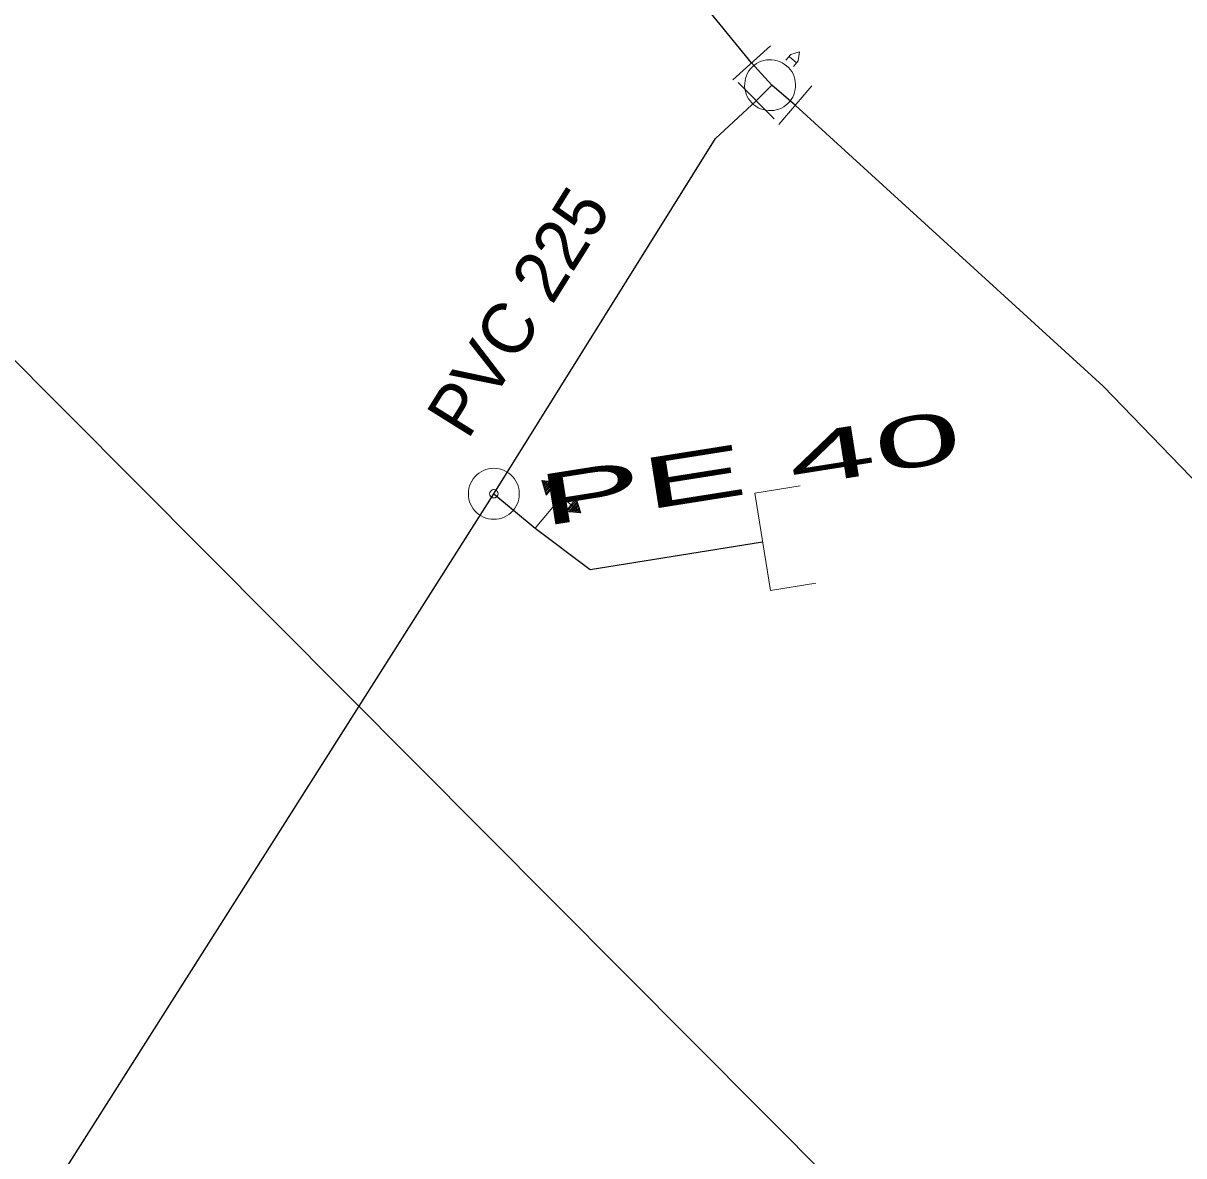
# Model space of a CAD drawing. Extents: x -659250 to -657316, y -997555 to -993684.
# Drawn here: x -658188.9 to -658166.14, y -996491.07 to -996468.86 of the extents above; entities that cross this region are included whole.
import ezdxf

# ---------------------------------------------------------------- set-up
doc = ezdxf.new("R2010")
doc.units = 0
doc.header["$LTSCALE"] = 0.4
doc.layers.add('1', color=7, linetype='Continuous')
for name, color, linetype, lineweight in [('14', 7, 'Continuous', 25), ('17', 7, 'Continuous', 25), ('23', 7, 'Continuous', 13), ('34', 7, 'Continuous', 13), ('42', 7, 'Continuous', 13), ('47', 7, 'Continuous', 13)]:
    doc.layers.add(name, color=color, linetype=linetype, lineweight=lineweight)

msp = doc.modelspace()

# ---------------------------------------------------------------- linework, layer by layer
at = {"layer": '14', "lineweight": 13}
msp.add_line((-658174.53, -996470.376), (-658174.221, -996470.07), dxfattribs=at)
at = {"layer": '14'}
msp.add_line((-658153.802, -996510.91), (-658194.34, -996470.18), dxfattribs=at)
at = {"layer": '17'}
for p, q in [((-658174.221, -996470.07), (-658174.617, -996469.633)), ((-658173.758, -996470.467), (-658174.221, -996470.07)), ((-658179.673, -996478.088), (-658178.86, -996478.761))]:
    msp.add_line(p, q, dxfattribs=at)
for points in [[(-658174.617, -996469.633), (-658187.469, -996453.91), (-658187.489, -996453.649)], [(-658179.673, -996478.088), (-658175.322, -996471.116), (-658174.53, -996470.376)], [(-658015.694, -996748.132), (-658012.013, -996715.116), (-658013.6, -996700.998), (-658031.362, -996648.688), (-658043.62, -996623.609), (-658054.721, -996612.745), (-658075.467, -996597.998), (-658101.14, -996577.425), (-658112.195, -996565.522), (-658140.875, -996516.98), (-658153.131, -996491.09), (-658167.719, -996475.975), (-658173.758, -996470.467)], [(-658341.671, -996632.003), (-658299.065, -996610.892), (-658296.028, -996615.664), (-658262.818, -996595.147), (-658215.971, -996543.456), (-658200.249, -996510.524), (-658179.673, -996478.088)], [(-658178.86, -996478.761), (-658177.783, -996479.576), (-658174.4, -996479.031)]]:
    msp.add_lwpolyline(points, dxfattribs=at)
at = {"layer": '23'}
msp.add_line((-658173.734, -996469.634), (-658173.883, -996469.506), dxfattribs=at)
for points in [[(-658173.946, -996469.58), (-658173.849, -996469.467), (-658173.675, -996469.417), (-658173.7, -996469.594), (-658173.797, -996469.708)], [(-658173.87, -996470.393), (-658173.838, -996470.351), (-658173.811, -996470.306), (-658173.79, -996470.259), (-658173.773, -996470.209), (-658173.761, -996470.159), (-658173.755, -996470.106), (-658173.754, -996470.054), (-658173.759, -996470.002), (-658173.768, -996469.951), (-658173.783, -996469.901), (-658173.804, -996469.852), (-658173.83, -996469.806), (-658173.859, -996469.763), (-658173.893, -996469.725), (-658173.931, -996469.689), (-658173.975, -996469.657), (-658174.018, -996469.63), (-658174.067, -996469.608), (-658174.114, -996469.591), (-658174.166, -996469.578), (-658174.219, -996469.573), (-658174.271, -996469.572), (-658174.324, -996469.577), (-658174.375, -996469.586), (-658174.424, -996469.602), (-658174.473, -996469.623), (-658174.518, -996469.648), (-658174.561, -996469.678), (-658174.6, -996469.713), (-658174.636, -996469.751), (-658174.668, -996469.792), (-658174.695, -996469.837), (-658174.717, -996469.885), (-658174.734, -996469.934), (-658174.744, -996469.985), (-658174.751, -996470.037), (-658174.753, -996470.089), (-658174.748, -996470.142), (-658174.738, -996470.193)], [(-658174.067, -996469.608), (-658174.114, -996469.591), (-658174.166, -996469.578), (-658174.219, -996469.573), (-658174.271, -996469.572), (-658174.324, -996469.577), (-658174.375, -996469.586), (-658174.424, -996469.602), (-658174.473, -996469.623), (-658174.518, -996469.648), (-658174.561, -996469.678), (-658174.6, -996469.713), (-658174.636, -996469.751), (-658174.668, -996469.792), (-658174.695, -996469.837), (-658174.717, -996469.885), (-658174.734, -996469.934), (-658174.744, -996469.985), (-658174.751, -996470.037), (-658174.753, -996470.089), (-658174.748, -996470.142), (-658174.738, -996470.193), (-658174.723, -996470.242), (-658174.702, -996470.291), (-658174.678, -996470.337), (-658174.646, -996470.38), (-658174.612, -996470.418), (-658174.574, -996470.454), (-658174.532, -996470.485), (-658174.488, -996470.513), (-658174.44, -996470.536), (-658174.39, -996470.552), (-658174.339, -996470.564), (-658174.288, -996470.571), (-658174.235, -996470.57), (-658174.183, -996470.567), (-658174.132, -996470.557), (-658174.081, -996470.541), (-658174.033, -996470.521), (-658173.987, -996470.495)], [(-658174.738, -996470.193), (-658174.723, -996470.242), (-658174.702, -996470.291), (-658174.678, -996470.337), (-658174.646, -996470.38), (-658174.612, -996470.418), (-658174.574, -996470.454), (-658174.532, -996470.485), (-658174.488, -996470.513), (-658174.44, -996470.536), (-658174.39, -996470.552), (-658174.339, -996470.564), (-658174.288, -996470.571), (-658174.235, -996470.57), (-658174.183, -996470.567), (-658174.132, -996470.557), (-658174.081, -996470.541), (-658174.033, -996470.521), (-658173.987, -996470.495), (-658173.945, -996470.464), (-658173.906, -996470.431), (-658173.87, -996470.393), (-658173.838, -996470.351), (-658173.811, -996470.306), (-658173.79, -996470.259), (-658173.773, -996470.209), (-658173.761, -996470.159), (-658173.755, -996470.106), (-658173.754, -996470.054), (-658173.759, -996470.002), (-658173.768, -996469.951), (-658173.783, -996469.901), (-658173.804, -996469.852), (-658173.83, -996469.806), (-658173.859, -996469.763), (-658173.893, -996469.725), (-658173.931, -996469.689), (-658173.975, -996469.657), (-658174.018, -996469.63), (-658174.067, -996469.608)], [(-658173.987, -996470.495), (-658173.945, -996470.464), (-658173.906, -996470.431), (-658173.87, -996470.393)]]:
    msp.add_lwpolyline(points, dxfattribs=at)
at = {"layer": '34'}
for p, q in [((-658174.246, -996469.297), (-658174.988, -996469.967)), ((-658174.882, -996470.021), (-658174.177, -996470.731)), ((-658173.432, -996470.087), (-658174.083, -996470.846)), ((-658178.648, -996478.114), (-658178.73, -996477.828)), ((-658178.702, -996477.83), (-658178.722, -996477.855)), ((-658178.67, -996477.837), (-658178.711, -996477.885)), ((-658178.639, -996477.838), (-658178.705, -996477.916)), ((-658178.612, -996477.84), (-658178.698, -996477.943)), ((-658178.58, -996477.847), (-658178.688, -996477.973)), ((-658178.553, -996477.849), (-658178.68, -996477.999)), ((-658178.524, -996477.853), (-658178.672, -996478.027)), ((-658178.492, -996477.853), (-658178.666, -996478.058)), ((-658178.462, -996477.859), (-658178.655, -996478.087)), ((-658178.348, -996478.145), (-658178.859, -996478.76)), ((-658178.047, -996478.204), (-658178.235, -996478.436)), ((-658178.035, -996478.233), (-658178.204, -996478.441)), ((-658178.03, -996478.263), (-658178.173, -996478.441)), ((-658178.02, -996478.291), (-658178.144, -996478.444)), ((-658178.013, -996478.318), (-658178.117, -996478.447)), ((-658178.001, -996478.347), (-658178.085, -996478.451)), ((-658177.993, -996478.374), (-658178.057, -996478.453)), ((-658177.987, -996478.404), (-658178.026, -996478.453)), ((-658177.974, -996478.434), (-658177.994, -996478.459))]:
    msp.add_line(p, q, dxfattribs=at)
for points in [[(-658178.73, -996477.828), (-658178.433, -996477.862), (-658178.648, -996478.114)], [(-658178.263, -996478.433), (-658177.967, -996478.461), (-658178.73, -996477.828)], [(-658177.967, -996478.461), (-658178.055, -996478.176), (-658178.263, -996478.433)]]:
    msp.add_lwpolyline(points, dxfattribs=at)
at = {"layer": '42'}
msp.add_lwpolyline([(-658173.664, -996477.934), (-658174.553, -996478.077), (-658174.247, -996479.984), (-658173.357, -996479.841)], dxfattribs=at)
at = {"layer": '47'}
for points in [[(-658179.173, -996478.088), (-658179.176, -996478.036), (-658179.184, -996477.983), (-658179.198, -996477.934), (-658179.215, -996477.885), (-658179.24, -996477.838), (-658179.269, -996477.794), (-658179.301, -996477.754), (-658179.338, -996477.717), (-658179.379, -996477.684), (-658179.423, -996477.655), (-658179.47, -996477.63), (-658179.519, -996477.613), (-658179.568, -996477.599), (-658179.62, -996477.591), (-658179.673, -996477.588), (-658179.725, -996477.591), (-658179.777, -996477.599), (-658179.828, -996477.613), (-658179.875, -996477.63), (-658179.923, -996477.655), (-658179.967, -996477.684), (-658180.007, -996477.717), (-658180.044, -996477.754), (-658180.078, -996477.794), (-658180.105, -996477.838), (-658180.13, -996477.885), (-658180.149, -996477.934), (-658180.161, -996477.983), (-658180.169, -996478.036), (-658180.173, -996478.088), (-658180.169, -996478.14), (-658180.161, -996478.192), (-658180.149, -996478.243), (-658180.13, -996478.291), (-658180.105, -996478.338), (-658180.078, -996478.382), (-658180.044, -996478.423), (-658180.007, -996478.46), (-658179.967, -996478.493), (-658179.923, -996478.521), (-658179.875, -996478.545), (-658179.828, -996478.564), (-658179.777, -996478.576), (-658179.725, -996478.585), (-658179.673, -996478.588), (-658179.62, -996478.585), (-658179.568, -996478.576), (-658179.519, -996478.564), (-658179.47, -996478.545), (-658179.423, -996478.521), (-658179.379, -996478.493), (-658179.338, -996478.46), (-658179.301, -996478.423), (-658179.269, -996478.382), (-658179.24, -996478.338), (-658179.215, -996478.291), (-658179.198, -996478.243), (-658179.184, -996478.192), (-658179.176, -996478.14)], [(-658179.59, -996478.088), (-658179.59, -996478.079), (-658179.593, -996478.071), (-658179.595, -996478.063), (-658179.598, -996478.054), (-658179.602, -996478.047), (-658179.607, -996478.04), (-658179.612, -996478.032), (-658179.617, -996478.027), (-658179.625, -996478.022), (-658179.632, -996478.017), (-658179.639, -996478.013), (-658179.647, -996478.01), (-658179.656, -996478.008), (-658179.664, -996478.005), (-658179.673, -996478.005), (-658179.681, -996478.005), (-658179.69, -996478.008), (-658179.698, -996478.01), (-658179.706, -996478.013), (-658179.713, -996478.017), (-658179.72, -996478.022), (-658179.728, -996478.027), (-658179.733, -996478.032), (-658179.74, -996478.04), (-658179.744, -996478.047), (-658179.747, -996478.054), (-658179.75, -996478.063), (-658179.752, -996478.071), (-658179.755, -996478.079), (-658179.755, -996478.088), (-658179.755, -996478.097), (-658179.752, -996478.105), (-658179.75, -996478.113), (-658179.747, -996478.121), (-658179.744, -996478.129), (-658179.74, -996478.136), (-658179.733, -996478.143), (-658179.728, -996478.149), (-658179.72, -996478.155), (-658179.713, -996478.159), (-658179.706, -996478.163), (-658179.698, -996478.166), (-658179.69, -996478.168), (-658179.681, -996478.17), (-658179.673, -996478.17), (-658179.664, -996478.17), (-658179.656, -996478.168), (-658179.647, -996478.166), (-658179.639, -996478.163), (-658179.632, -996478.159), (-658179.625, -996478.155), (-658179.617, -996478.149), (-658179.612, -996478.143), (-658179.607, -996478.136), (-658179.602, -996478.129), (-658179.598, -996478.121), (-658179.595, -996478.113), (-658179.593, -996478.105), (-658179.59, -996478.097)]]:
    msp.add_lwpolyline(points, close=True, dxfattribs=at)

# ---------------------------------------------------------------- texts
at = {"layer": '1'}
msp.add_text('PVC 225 ', height=1, rotation=58, dxfattribs=at).set_placement((-658180.185, -996477.048))
at = {"layer": '1', "width": 2.3}
msp.add_text('PE 40 ', height=1, rotation=9, dxfattribs=at).set_placement((-658178.715, -996478.727))

doc.saveas('drawing.dxf')
